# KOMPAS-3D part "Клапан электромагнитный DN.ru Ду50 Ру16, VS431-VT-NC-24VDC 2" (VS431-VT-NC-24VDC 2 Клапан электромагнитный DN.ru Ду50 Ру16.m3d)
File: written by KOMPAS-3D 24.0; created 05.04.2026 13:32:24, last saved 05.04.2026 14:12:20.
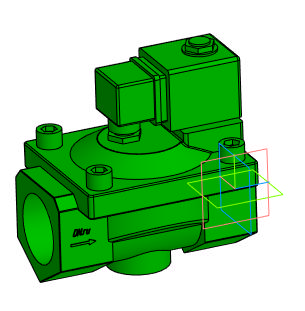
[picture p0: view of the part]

Document properties: Автор: artio; Полное имя файла: C:\Users\artio\OneDrive\Рабочий стол\Клапан электромагнитный DN.ru\VS431\VS431-VT-NC\VS431-VT-NC-24VDC\Ду50\VS431-VT-NC-24VDC 2 Клапан электромагнитный DN.ru Ду50 Ру16.m3d

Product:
- Body: Тело 1  | qty 1
    Масса: 6.703651
- Part/product: Клапан электромагнитный DN.ru Ду50 Ру16  | designation VS431-VT-NC-24VDC 2
    Масса: 3.341
    Раздел спецификации: Прочие изделия
    Примечание: D130-04759
    additional columns: ef56311e-7521-43dc-8291-0e6108b3d81d; artio; c; Шероховатость не задана; Да

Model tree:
1. Операция без истории:1

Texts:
  VS431-VT-NC-24VDC 2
